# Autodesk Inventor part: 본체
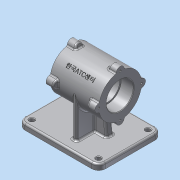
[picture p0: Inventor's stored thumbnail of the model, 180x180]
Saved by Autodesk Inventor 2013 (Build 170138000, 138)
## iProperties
Created: 2015-12
Part Number: 본체
Material: 알루미늄 6061
Document SubType Name: Modeling
Designer: Administrator
Density: 2.71 g/cm^3
Mass: 1142.91 g
Surface Area: 797.148 cm^2
Volume: 421.737 cm^3
Author: Administrator
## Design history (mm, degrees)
sketch "스케치1"
  geometry: L1 (-70, 55)-(70, 55); L2 (70, 55)-(70, -55); L3 (70, -55)-(-70, -55); L4 (-70, -55)-(-70, 55); 3 further points
  constraints: 8 end point, 2 midpoint, 2 parallel, 1 horizontal, 1 horizontal alignment, 1 perpendicular, 1 vertical alignment
  dimensions: "d0" = 140 distance of L1.start L1.end; "d2" = 110 distance of L1.end L2.end
extrude "돌출1" new body sketch "스케치1" distance "d3" = 10; taper "d4" = 0 deg
node "작업 평면1"
sketch "스케치2"
  geometry: L1 (0, 110)-(0, 0) reference; C1 r 37 at (80, 55); 2 further points
  constraints: 1 centre point, 1 horizontal alignment, 1 midpoint
  dimensions: "d6" = 74 diameter of C1; "d111" = 80 distance of point (0, 55) C1.centre
extrude "돌출2" join sketch "스케치2" stored distance "d8" = 85; taper "d9" = 0 deg
sketch "스케치3"
  geometry: L1 (0, 0)-(0, 110) reference; L2 (0, 0)-(10, 0) reference; L3 (10, 110)-(10, 0) reference; L4 (0, 110)-(10, 110) reference; L5 (0, 110)-(10, 110) reference; L6 (10, 110)-(10, 0) reference; L7 (10, 0)-(0, 0) reference; L8 (0, 0)-(0, 110) reference; L9 (10, 18)-(80, 18); L10 (10, 92)-(80, 92); L11 (80, 18)-(80, 92); A1 r 37 centre (80, 55) between (80, 92) and (80, 18) reference; 1 further point
  constraints: 6 end point, 2 perpendicular, 2 point on circle, 2 point on line, 2 tangent, 1 parallel
extrude "돌출3" join sketch "스케치3" stored distance "d10" = 8; taper "d11" = 0 deg
sketch "스케치4"
  geometry: L1 (70, 10)-(70, 0) reference; L2 (70, 0)-(-70, 0) reference; L3 (-70, 0)-(-70, 10) reference; L4 (-70, 10)-(-14, 10) reference; L5 (-14, 10)-(-14, 43) reference; L6 (-14, 43)-(-52.5, 43) reference; L7 (-52.5, 43)-(-52.5, 117) reference; L8 (-52.5, 117)-(32.5, 117) reference; L9 (32.5, 117)-(32.5, 43) reference; L10 (32.5, 43)-(-6, 43) reference; L11 (-6, 43)-(-6, 10) reference; L12 (-6, 10)-(70, 10) reference; L13 (-28.245, 65.019)-(8.245, 65.019); L14 (-28.245, 65.019)-(-35, 10); L15 (8.245, 65.019)-(15, 10); L16 (-35, 10)-(15, 10); 3 further points
  constraints: 8 end point, 2 midpoint, 2 point on line, 1 collinear, 1 parallel, 1 vertical alignment
  dimensions: "d15" = 97 deg angle of L4 L14; "d16" = 97 deg angle of L12 L15; "d17" = 50 distance of L15.end L14.end; "d19" = 55.01908 distance between parallel lines of L12 L13
extrude "돌출4" join sketch "스케치4" stored distance "d20" = 12; taper "d21" = 0 deg
sketch "스케치5"
  geometry: L1 (70, -55)-(70, 55) reference; L2 (70, 55)-(80, 55) reference; L3 (80, 55)-(80, -55) reference; L4 (80, -55)-(70, -55) reference; L5 (-37, -7)-(-36.332, -7); L6 (-37, 7)-(-36.332, 7); A1 r 37 centre (0, 0) between (-37, 0) and (-36.332, -7) reference; A2 r 7 centre (-37, 0) between (-37, 7) and (-37, -7); 1 further point
  constraints: 5 point on circle, 4 end point, 2 parallel, 2 tangent, 1 centre point, 1 horizontal alignment
  dimensions: "d22" = 14 diameter of A2
extrude "돌출5" join sketch "스케치5" distance "d25" = 15; taper "d26" = 0 deg
feature "면 기울기1" dims angle "d27" = 20 deg
hole "구멍1" diameter "d33" = 42; stored, may be unused: countersink angle "d37" = 90 deg, drill point angle "d39" = 0 deg; dims "d31" = 10, "d32" = 10, "d34" = 6, "d35" = 47, "d36" = 22, "d38" = 63
hole "구멍2" diameter "d42" = 47; stored, may be unused: countersink angle "d46" = 90 deg, drill point angle "d48" = 0 deg; dims "d40" = 10, "d41" = 10, "d43" = 6, "d44" = 47, "d45" = 22, "d47" = 22
hole "구멍3" diameter "d51" = 3.242; stored, may be unused: countersink angle "d55" = 90 deg, drill point angle "d57" = 118 deg; dims "d49" = 10, "d50" = 10, "d52" = 9, "d53" = 47, "d54" = 22, "d56" = 11
hole "구멍4" diameter "d63" = 3.242; stored, may be unused: countersink angle "d67" = 90 deg, drill point angle "d69" = 118 deg; dims "d61" = 10, "d62" = 10, "d64" = 9, "d65" = 47, "d66" = 22, "d68" = 11
sketch "스케치6"
  geometry: L1 (6, -6)-(-15, -6) reference; L2 (-15, -6)-(-15, 6) reference; L3 (-15, 6)-(6, 6) reference; L4 (6, 6)-(6, 37) reference; L5 (6, 37)-(14, 37) reference; L6 (14, 37)-(14, 6) reference; L7 (14, 6)-(35, 6) reference; L8 (35, 6)-(35, -6) reference; L9 (35, -6)-(14, -6) reference; L10 (14, -6)-(14, -37) reference; L11 (14, -37)-(6, -37) reference; L12 (6, -37)-(6, -6) reference; L13 (70, 55)-(70, -55) reference; L14 (70, -55)-(-70, -55) reference; L15 (-70, -55)-(-70, 55) reference; L16 (-70, 55)-(70, 55) reference; C1 r 4 at (-58, 43); C2 r 4 at (58, 43); C3 r 4 at (-58, -43); C4 r 4 at (58, -43); 1 further point
  constraints: 4 centre point, 3 equal radius, 2 horizontal alignment, 2 vertical alignment
  dimensions: "d73" = 12 distance from line of C1.centre L15; "d74" = 12 distance from line of L16 C1.centre; "d76" = 116 distance of C2.centre C1.centre; "d77" = 86 distance of C1.centre C3.centre; "d78" = 8 diameter of C1
  node "절단 모서리 투영4"
extrude "돌출6" cut sketch "스케치6" stored distance "d79" = 15; taper "d80" = 0 deg
extrude "돌출7" cut sketch "스케치6" stored distance "d81" = 15; taper "d82" = 0 deg
extrude "돌출8" cut sketch "스케치6" stored distance "d83" = 15; taper "d84" = 0 deg
extrude "돌출9" cut sketch "스케치6" distance "d85" = 15; taper "d86" = 0 deg
fillet "모깎기1" dims "d87" = 12
fillet "모깎기2" dims "d88" = 3
fillet "모깎기3" dims "d89" = 3
fillet "모깎기4" dims "d90" = 3
fillet "모깎기5" dims "d91" = 3
fillet "모깎기6" dims "d92" = 3
fillet "모깎기7" dims "d93" = 3
fillet "모깎기8" dims "d94" = 3
fillet "모깎기9" dims "d95" = 3
fillet "모깎기10" dims "d96" = 0.3
chamfer "모따기1" distance "d97" = 1; stored, may be unused: second distance "d98" = 2, angle "d99" = 45 deg
sketch "스케치10"
  geometry: L1 (13, 92)-(80, 92) reference; L2 (80, 18)-(13, 18) reference; L3 (10, 15)-(10, 3) reference; L4 (7, 0)-(0, 0) reference; L5 (0, 0)-(0, 110) reference; L6 (0, 110)-(7, 110) reference; L7 (10, 107)-(10, 95) reference; C1 r 21 at (80, 55) reference; A1 r 3 centre (13, 95) between (10, 95) and (13, 92) reference; A2 r 37 centre (80, 55) between (80, 18) and (80, 92) reference; A3 r 3 centre (13, 15) between (13, 18) and (10, 15) reference; A4 r 3 centre (7, 3) between (7, 0) and (10, 3) reference; A5 r 3 centre (7, 107) between (10, 107) and (7, 110) reference; 3 further points
  constraints: 1 coincident, 1 point on circle
  dimensions: "d106" = 45 deg dimension on A2.centre point (106.163, 28.837) point (80, 18)
  node "절단 모서리 투영7"
node "작업 평면3"
sketch "스케치11"
  geometry: L1 (-24.887, 3.602)-(24.887, 3.602); L2 (24.887, 3.602)-(24.887, -3.602); L3 (24.887, -3.602)-(-24.887, -3.602); L4 (-24.887, -3.602)-(-24.887, 3.602); 5 further points
  constraints: 2 midpoint, 1 coincident, 1 horizontal alignment, 1 vertical, 1 vertical alignment, 2 other
  dimensions: "d107" = 49.77477 distance from line of L1.end L4; "d108" = 3.60244 distance from line of point (-24.887, 0) L1
feature "엠보싱2" sketch "스케치11" dims "d109" = 0.5, "d110" = 0
chamfer "모따기2" distance "d112" = 1; stored, may be unused: second distance "d113" = 2, angle "d114" = 45 deg
chamfer "모따기3" distance "d115" = 1; stored, may be unused: second distance "d116" = 2, angle "d117" = 45 deg
node "솔리드1"
pattern_circular "원형 패턴1" dims angle "d29" = 360 deg
mirror "대칭1"
pattern_circular "원형 패턴2" dims angle "d59" = 360 deg
pattern_circular "원형 패턴3" dims angle "d71" = 360 deg
node "투영된 루프1"
node "절단 모서리 투영1"
node "절단 모서리 투영2"
node "절단 모서리 투영3"
